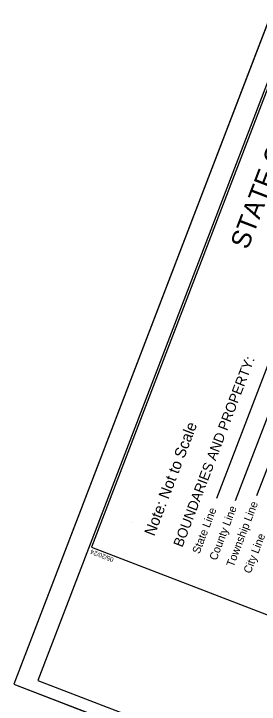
# Model space of a CAD drawing. Extents: x 1015221 to 1064345, y 619216 to 647967.
# Drawn here: x 1042814 to 1044921, y 624619 to 630539 of the extents above; entities that cross this region are included whole.
import ezdxf

# ---------------------------------------------------------------- set-up
doc = ezdxf.new("R2010")
doc.units = 0
for name, color, linetype in [('Default', 7, 'Continuous'), ('Sheet Cutting Line CELL', 7, 'Continuous'), ('Sheet Plot Border Inside CELL', 7, 'Continuous'), ('Sheet Plot Border Outside CELL', 7, 'Continuous'), ('Sheet Symbology CELL', 7, 'Continuous')]:
    doc.layers.add(name, color=color, linetype=linetype)

msp = doc.modelspace()

# ---------------------------------------------------------------- linework, layer by layer
at = {"layer": 'Default'}
for p, q in [((1045088.1, 627774.6), (1044553.5, 626383.1)), ((1045234.6, 627718.3), (1044714, 626363.4)), ((1045381, 627662.1), (1044897.9, 626404.5)), ((1043832.6, 626180.8), (1043832.6, 626180.8))]:
    msp.add_line(p, q, dxfattribs=at)
at = {"layer": 'Sheet Cutting Line CELL'}
for p, q in [((1047645.6, 637365.6), (1042813.9, 624789.8)), ((1042813.9, 624789.8), (1051028.5, 621633.8))]:
    msp.add_line(p, q, dxfattribs=at)
at = {"layer": 'Sheet Plot Border Inside CELL'}
msp.add_lwpolyline([(1050898.2, 621795.3), (1055679.6, 634240.3), (1047800.3, 637267.6), (1043018.9, 624822.5)], close=True, dxfattribs=at)
at = {"layer": 'Sheet Plot Border Outside CELL'}
msp.add_lwpolyline([(1051028.5, 621633.8), (1055860.2, 634209.5), (1047645.6, 637365.6), (1042813.9, 624789.8)], close=True, dxfattribs=at)
at = {"layer": 'Sheet Symbology CELL'}
msp.add_lwpolyline([(1047783.5, 637166.9), (1043479.8, 625965.2), (1051313.4, 622955.5), (1055617.1, 634157.2)], close=True, dxfattribs=at)

# ---------------------------------------------------------------- texts
at = {"layer": 'Default'}
for s, height, rotation, p in [('STATE OF NORTH CAROLINA, DIVISION OF HIGHWAYS', 163.31, 68.98302, (1044821.1, 628509.7)), ('BOUNDARIES AND PROPERTY:', 86.308, 68.98302, (1044260.5, 625958.6)), ('Note: Not to Scale', 94.998, 68.98302, (1044019.6, 626054)), ('Township Line', 68.654, 68.98302, (1044699.9, 625789.9)), ('State Line', 68.65, 68.98302, (1044406.9, 625902.4)), ('County Line', 68.654, 68.98302, (1044553.4, 625846.1)), ('City Line', 68.65, 68.98302, (1044846.4, 625733.6)), ('05/20/24', 38.88, 158.98302, (1043675.3, 625872))]:
    msp.add_text(s, height=height, rotation=rotation, dxfattribs=at).set_placement(p)

doc.saveas('drawing.dxf')
